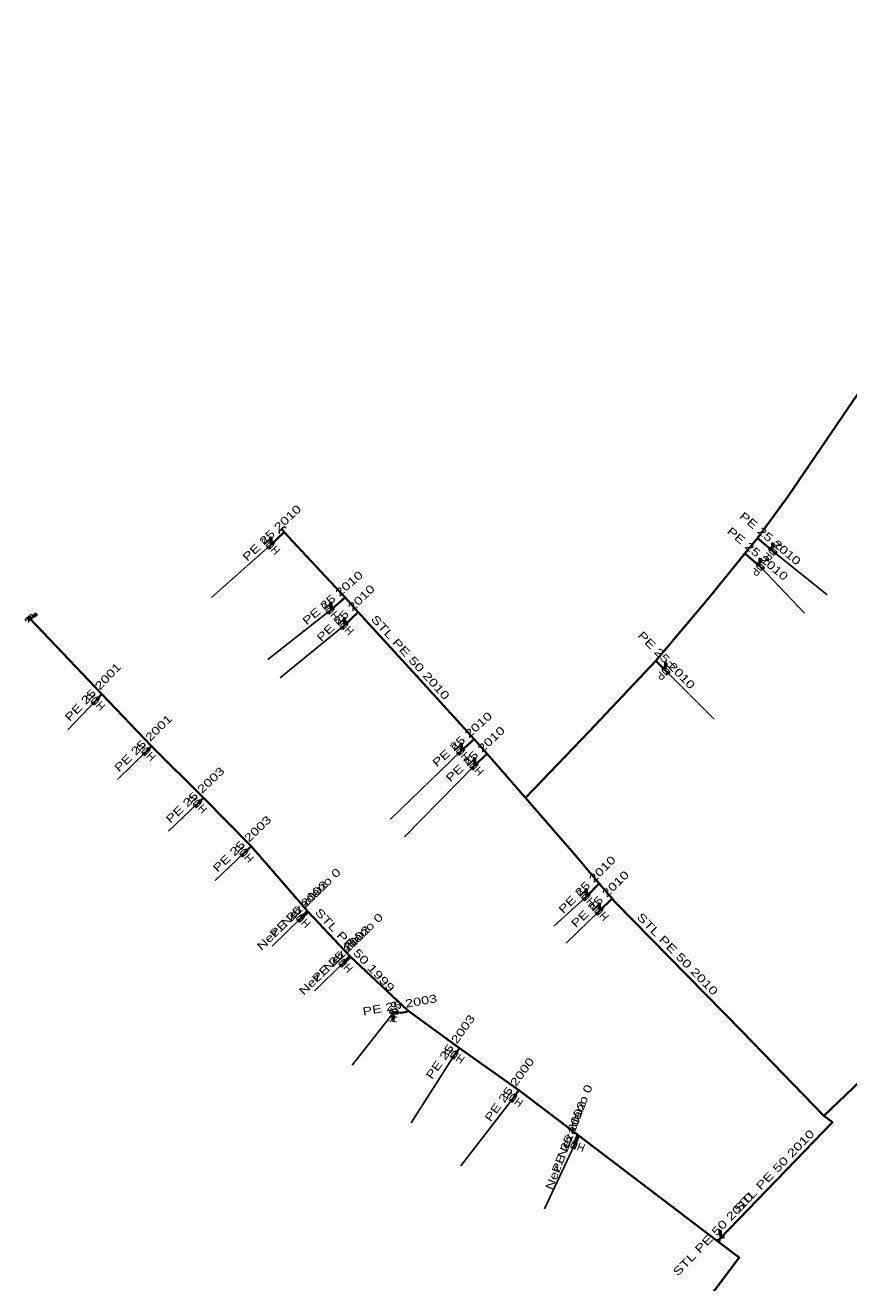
# Model space of a CAD drawing. Extents: x -737484 to -734496, y -1033882 to -1030666.
# Drawn here: x -736564.5 to -736461.6, y -1032578.8 to -1032421.6 of the extents above; entities that cross this region are included whole.
import ezdxf
from ezdxf.enums import TextEntityAlignment as Align

# ---------------------------------------------------------------- set-up
doc = ezdxf.new("R2010")
doc.units = 0
doc.header["$LTSCALE"] = 0.4
for name, color, linetype, lineweight in [('1', 7, 'Continuous', 13), ('18', 7, 'Continuous', 60), ('22', 7, 'Continuous', 25), ('5', 7, 'Continuous', 35), ('7', 7, 'Continuous', 35)]:
    doc.layers.add(name, color=color, linetype=linetype, lineweight=lineweight)
doc.layers.add('2', color=7, linetype='Continuous')

msp = doc.modelspace()

# ---------------------------------------------------------------- linework, layer by layer
at = {"layer": '1'}
for p, q in [((-736533.782, -1032486.023), (-736533.782, -1032485.673)), ((-736533.857, -1032486.598), (-736533.857, -1032486.098)), ((-736471.104, -1032487.331), (-736471.104, -1032486.831)), ((-736471.029, -1032486.756), (-736471.029, -1032486.406)), ((-736472.67, -1032489.253), (-736472.67, -1032488.753)), ((-736472.595, -1032488.678), (-736472.595, -1032488.328)), ((-736526.285, -1032494.161), (-736526.285, -1032493.811)), ((-736563.44, -1032495.519), (-736563.15, -1032495.323)), ((-736526.36, -1032494.736), (-736526.36, -1032494.236)), ((-736564.094, -1032496.258), (-736563.957, -1032495.778)), ((-736563.959, -1032495.779), (-736563.544, -1032495.499)), ((-736524.638, -1032496.644), (-736524.638, -1032496.144)), ((-736524.563, -1032496.069), (-736524.563, -1032495.719)), ((-736484.39, -1032501.721), (-736484.39, -1032501.371)), ((-736484.465, -1032502.296), (-736484.465, -1032501.796)), ((-736510.072, -1032512.351), (-736510.072, -1032511.851)), ((-736509.997, -1032511.776), (-736509.997, -1032511.426)), ((-736508.406, -1032514.191), (-736508.406, -1032513.691)), ((-736508.331, -1032513.616), (-736508.331, -1032513.266)), ((-736494.345, -1032529.963), (-736494.345, -1032529.613)), ((-736494.42, -1032530.538), (-736494.42, -1032530.038)), ((-736492.719, -1032531.76), (-736492.719, -1032531.41)), ((-736492.794, -1032532.335), (-736492.794, -1032531.835)), ((-736518.574, -1032545.488), (-736518.623, -1032545.835)), ((-736518.42, -1032544.93), (-736518.489, -1032545.425)), ((-736477.601, -1032572.67), (-736477.601, -1032572.32)), ((-736477.676, -1032573.245), (-736477.676, -1032572.745))]:
    msp.add_line(p, q, dxfattribs=at)
for points in [[(-736532.645, -1032485.123), (-736532.818, -1032484.942), (-736532.095, -1032484.251), (-736531.922, -1032484.432)], [(-736564.355, -1032496.086), (-736564.528, -1032495.906), (-736563.809, -1032495.211), (-736563.635, -1032495.391)]]:
    msp.add_lwpolyline(points, dxfattribs=at)
for points in [[(-736533.857, -1032485.598), (-736534.007, -1032485.598), (-736534.007, -1032486.098), (-736533.857, -1032486.098)], [(-736533.857, -1032485.598), (-736533.707, -1032485.598), (-736533.707, -1032486.098), (-736533.857, -1032486.098)], [(-736533.82, -1032485.636), (-736533.745, -1032485.636), (-736533.745, -1032486.061), (-736533.82, -1032486.061)], [(-736534.077, -1032487.089), (-736534.355, -1032486.801), (-736533.358, -1032486.394), (-736533.636, -1032486.106)], [(-736470.592, -1032487.499), (-736470.849, -1032487.805), (-736471.358, -1032486.856), (-736471.615, -1032487.162)], [(-736471.104, -1032486.331), (-736471.254, -1032486.331), (-736471.254, -1032486.831), (-736471.104, -1032486.831)], [(-736471.104, -1032486.331), (-736470.954, -1032486.331), (-736470.954, -1032486.831), (-736471.104, -1032486.831)], [(-736471.067, -1032486.369), (-736470.992, -1032486.369), (-736470.992, -1032486.794), (-736471.067, -1032486.794)], [(-736472.158, -1032489.421), (-736472.415, -1032489.727), (-736472.924, -1032488.778), (-736473.181, -1032489.084)], [(-736472.67, -1032488.253), (-736472.82, -1032488.253), (-736472.82, -1032488.753), (-736472.67, -1032488.753)], [(-736472.67, -1032488.253), (-736472.52, -1032488.253), (-736472.52, -1032488.753), (-736472.67, -1032488.753)], [(-736472.633, -1032488.291), (-736472.558, -1032488.291), (-736472.558, -1032488.716), (-736472.633, -1032488.716)], [(-736526.36, -1032493.736), (-736526.51, -1032493.736), (-736526.51, -1032494.236), (-736526.36, -1032494.236)], [(-736526.36, -1032493.736), (-736526.21, -1032493.736), (-736526.21, -1032494.236), (-736526.36, -1032494.236)], [(-736526.323, -1032493.774), (-736526.248, -1032493.774), (-736526.248, -1032494.199), (-736526.323, -1032494.199)], [(-736563.129, -1032495.219), (-736563.213, -1032495.095), (-736563.628, -1032495.375), (-736563.544, -1032495.499)], [(-736563.129, -1032495.219), (-736563.046, -1032495.344), (-736563.46, -1032495.623), (-736563.544, -1032495.499)], [(-736563.14, -1032495.271), (-736563.098, -1032495.333), (-736563.451, -1032495.571), (-736563.493, -1032495.509)], [(-736526.606, -1032495.214), (-736526.868, -1032494.913), (-736525.851, -1032494.558), (-736526.113, -1032494.257)], [(-736564.014, -1032496.021), (-736564.037, -1032496.015), (-736564.06, -1032496.005), (-736564.082, -1032495.994), (-736564.102, -1032495.98), (-736564.122, -1032495.965), (-736564.139, -1032495.949), (-736564.155, -1032495.93), (-736564.169, -1032495.909), (-736564.181, -1032495.888), (-736564.191, -1032495.865), (-736564.198, -1032495.843), (-736564.203, -1032495.818), (-736564.206, -1032495.793), (-736564.207, -1032495.769), (-736564.204, -1032495.745), (-736564.2, -1032495.72), (-736564.193, -1032495.696), (-736564.184, -1032495.674), (-736564.173, -1032495.652), (-736564.159, -1032495.631), (-736564.144, -1032495.612), (-736564.127, -1032495.595), (-736564.109, -1032495.579), (-736564.088, -1032495.565), (-736564.067, -1032495.552), (-736564.044, -1032495.543), (-736564.02, -1032495.536), (-736563.997, -1032495.531), (-736563.972, -1032495.527), (-736563.948, -1032495.527), (-736563.924, -1032495.529), (-736563.899, -1032495.534), (-736563.876, -1032495.54), (-736563.853, -1032495.549), (-736563.831, -1032495.561), (-736563.811, -1032495.574), (-736563.791, -1032495.59), (-736563.773, -1032495.606), (-736563.758, -1032495.625), (-736563.744, -1032495.645), (-736563.731, -1032495.667), (-736563.722, -1032495.69), (-736563.714, -1032495.713), (-736563.71, -1032495.737), (-736563.706, -1032495.761), (-736563.706, -1032495.786), (-736563.708, -1032495.81), (-736563.713, -1032495.834), (-736563.719, -1032495.858), (-736563.728, -1032495.881), (-736563.74, -1032495.903), (-736563.753, -1032495.923), (-736563.769, -1032495.943), (-736563.785, -1032495.961), (-736563.804, -1032495.976), (-736563.824, -1032495.99), (-736563.846, -1032496.002), (-736563.869, -1032496.012), (-736563.892, -1032496.02), (-736563.916, -1032496.024), (-736563.941, -1032496.027), (-736563.965, -1032496.028), (-736563.989, -1032496.025)], [(-736563.786, -1032495.817), (-736563.79, -1032495.833), (-736563.796, -1032495.849), (-736563.805, -1032495.865), (-736563.814, -1032495.88), (-736563.824, -1032495.893), (-736563.837, -1032495.905), (-736563.85, -1032495.916), (-736563.864, -1032495.926), (-736563.879, -1032495.935), (-736563.894, -1032495.942), (-736563.911, -1032495.946), (-736563.928, -1032495.95), (-736563.945, -1032495.952), (-736563.962, -1032495.953), (-736563.979, -1032495.951), (-736563.996, -1032495.948), (-736564.012, -1032495.944), (-736564.029, -1032495.937), (-736564.044, -1032495.929), (-736564.059, -1032495.92), (-736564.072, -1032495.909), (-736564.084, -1032495.897), (-736564.095, -1032495.884), (-736564.105, -1032495.87), (-736564.114, -1032495.854), (-736564.121, -1032495.839), (-736564.125, -1032495.823), (-736564.129, -1032495.806), (-736564.131, -1032495.789), (-736564.131, -1032495.771), (-736564.13, -1032495.754), (-736564.127, -1032495.737), (-736564.122, -1032495.721), (-736564.116, -1032495.705), (-736564.108, -1032495.689), (-736564.099, -1032495.675), (-736564.088, -1032495.662), (-736564.076, -1032495.65), (-736564.063, -1032495.638), (-736564.049, -1032495.628), (-736564.033, -1032495.62), (-736564.018, -1032495.613), (-736564.001, -1032495.608), (-736563.985, -1032495.604), (-736563.968, -1032495.603), (-736563.95, -1032495.603), (-736563.934, -1032495.604), (-736563.916, -1032495.607), (-736563.9, -1032495.612), (-736563.884, -1032495.618), (-736563.868, -1032495.626), (-736563.854, -1032495.635), (-736563.841, -1032495.645), (-736563.828, -1032495.657), (-736563.817, -1032495.671), (-736563.807, -1032495.685), (-736563.799, -1032495.7), (-736563.792, -1032495.715), (-736563.788, -1032495.732), (-736563.783, -1032495.749), (-736563.782, -1032495.766), (-736563.781, -1032495.783), (-736563.782, -1032495.8)], [(-736564.103, -1032495.743), (-736564.098, -1032495.728), (-736564.093, -1032495.716), (-736564.087, -1032495.702), (-736564.078, -1032495.69), (-736564.07, -1032495.678), (-736564.059, -1032495.668), (-736564.047, -1032495.658), (-736564.035, -1032495.65), (-736564.023, -1032495.643), (-736564.009, -1032495.637), (-736563.995, -1032495.632), (-736563.981, -1032495.629), (-736563.965, -1032495.627), (-736563.951, -1032495.627), (-736563.937, -1032495.628), (-736563.922, -1032495.631), (-736563.907, -1032495.636), (-736563.894, -1032495.64), (-736563.881, -1032495.647), (-736563.868, -1032495.655), (-736563.857, -1032495.664), (-736563.847, -1032495.675), (-736563.837, -1032495.686), (-736563.829, -1032495.699), (-736563.821, -1032495.711), (-736563.815, -1032495.724), (-736563.811, -1032495.739), (-736563.808, -1032495.753), (-736563.806, -1032495.768), (-736563.806, -1032495.782), (-736563.807, -1032495.797), (-736563.81, -1032495.811), (-736563.814, -1032495.826), (-736563.819, -1032495.84), (-736563.826, -1032495.852), (-736563.834, -1032495.865), (-736563.843, -1032495.877), (-736563.854, -1032495.887), (-736563.865, -1032495.896), (-736563.877, -1032495.905), (-736563.89, -1032495.912), (-736563.903, -1032495.918), (-736563.918, -1032495.923), (-736563.932, -1032495.926), (-736563.946, -1032495.927), (-736563.961, -1032495.927), (-736563.976, -1032495.926), (-736563.99, -1032495.924), (-736564.005, -1032495.92), (-736564.018, -1032495.914), (-736564.031, -1032495.907), (-736564.043, -1032495.899), (-736564.056, -1032495.891), (-736564.066, -1032495.88), (-736564.075, -1032495.868), (-736564.084, -1032495.856), (-736564.091, -1032495.844), (-736564.096, -1032495.83), (-736564.102, -1032495.816), (-736564.105, -1032495.802), (-736564.106, -1032495.787), (-736564.107, -1032495.772), (-736564.105, -1032495.758)], [(-736564.029, -1032495.76), (-736564.027, -1032495.753), (-736564.025, -1032495.747), (-736564.022, -1032495.74), (-736564.017, -1032495.734), (-736564.013, -1032495.728), (-736564.007, -1032495.722), (-736564.002, -1032495.718), (-736563.995, -1032495.713), (-736563.989, -1032495.71), (-736563.983, -1032495.706), (-736563.975, -1032495.705), (-736563.969, -1032495.703), (-736563.961, -1032495.702), (-736563.954, -1032495.702), (-736563.946, -1032495.702), (-736563.94, -1032495.704), (-736563.932, -1032495.707), (-736563.925, -1032495.708), (-736563.919, -1032495.712), (-736563.912, -1032495.716), (-736563.907, -1032495.721), (-736563.901, -1032495.726), (-736563.896, -1032495.731), (-736563.892, -1032495.738), (-736563.889, -1032495.744), (-736563.886, -1032495.751), (-736563.883, -1032495.758), (-736563.882, -1032495.765), (-736563.881, -1032495.773), (-736563.881, -1032495.78), (-736563.882, -1032495.787), (-736563.883, -1032495.794), (-736563.885, -1032495.801), (-736563.888, -1032495.808), (-736563.891, -1032495.815), (-736563.895, -1032495.821), (-736563.9, -1032495.827), (-736563.904, -1032495.832), (-736563.911, -1032495.837), (-736563.916, -1032495.841), (-736563.923, -1032495.844), (-736563.93, -1032495.848), (-736563.937, -1032495.85), (-736563.944, -1032495.852), (-736563.951, -1032495.853), (-736563.959, -1032495.853), (-736563.966, -1032495.852), (-736563.973, -1032495.851), (-736563.981, -1032495.848), (-736563.987, -1032495.846), (-736563.994, -1032495.843), (-736564, -1032495.839), (-736564.006, -1032495.834), (-736564.011, -1032495.829), (-736564.016, -1032495.823), (-736564.02, -1032495.817), (-736564.023, -1032495.81), (-736564.027, -1032495.804), (-736564.028, -1032495.796), (-736564.031, -1032495.79), (-736564.031, -1032495.782), (-736564.032, -1032495.775), (-736564.031, -1032495.768)], [(-736524.858, -1032497.135), (-736525.136, -1032496.847), (-736524.139, -1032496.44), (-736524.417, -1032496.152)], [(-736524.638, -1032495.644), (-736524.788, -1032495.644), (-736524.788, -1032496.144), (-736524.638, -1032496.144)], [(-736524.638, -1032495.644), (-736524.488, -1032495.644), (-736524.488, -1032496.144), (-736524.638, -1032496.144)], [(-736524.601, -1032495.682), (-736524.526, -1032495.682), (-736524.526, -1032496.107), (-736524.601, -1032496.107)], [(-736484.465, -1032501.296), (-736484.615, -1032501.296), (-736484.615, -1032501.796), (-736484.465, -1032501.796)], [(-736484.465, -1032501.296), (-736484.315, -1032501.296), (-736484.315, -1032501.796), (-736484.465, -1032501.796)], [(-736484.428, -1032501.334), (-736484.353, -1032501.334), (-736484.353, -1032501.759), (-736484.428, -1032501.759)], [(-736483.97, -1032502.508), (-736484.252, -1032502.79), (-736484.677, -1032501.801), (-736484.959, -1032502.083)], [(-736555.932, -1032506.558), (-736556.22, -1032506.28), (-736555.237, -1032505.839), (-736555.525, -1032505.561)], [(-736549.622, -1032512.874), (-736549.904, -1032512.592), (-736548.915, -1032512.167), (-736549.197, -1032511.885)], [(-736510.309, -1032512.834), (-736510.577, -1032512.536), (-736509.566, -1032512.165), (-736509.834, -1032511.867)], [(-736510.072, -1032511.351), (-736510.222, -1032511.351), (-736510.222, -1032511.851), (-736510.072, -1032511.851)], [(-736510.072, -1032511.351), (-736509.922, -1032511.351), (-736509.922, -1032511.851), (-736510.072, -1032511.851)], [(-736510.035, -1032511.389), (-736509.96, -1032511.389), (-736509.96, -1032511.814), (-736510.035, -1032511.814)], [(-736508.635, -1032514.678), (-736508.908, -1032514.385), (-736507.903, -1032513.996), (-736508.176, -1032513.703)], [(-736508.406, -1032513.191), (-736508.556, -1032513.191), (-736508.556, -1032513.691), (-736508.406, -1032513.691)], [(-736508.406, -1032513.191), (-736508.256, -1032513.191), (-736508.256, -1032513.691), (-736508.406, -1032513.691)], [(-736508.369, -1032513.229), (-736508.294, -1032513.229), (-736508.294, -1032513.654), (-736508.369, -1032513.654)], [(-736543.198, -1032519.376), (-736543.471, -1032519.083), (-736542.466, -1032518.694), (-736542.739, -1032518.401)], [(-736537.379, -1032525.541), (-736537.657, -1032525.253), (-736536.66, -1032524.846), (-736536.938, -1032524.558)], [(-736494.42, -1032529.538), (-736494.57, -1032529.538), (-736494.57, -1032530.038), (-736494.42, -1032530.038)], [(-736494.42, -1032529.538), (-736494.27, -1032529.538), (-736494.27, -1032530.038), (-736494.42, -1032530.038)], [(-736494.383, -1032529.576), (-736494.308, -1032529.576), (-736494.308, -1032530.001), (-736494.383, -1032530.001)], [(-736494.632, -1032531.032), (-736494.914, -1032530.75), (-736493.925, -1032530.325), (-736494.207, -1032530.043)], [(-736492.794, -1032531.335), (-736492.944, -1032531.335), (-736492.944, -1032531.835), (-736492.794, -1032531.835)], [(-736492.794, -1032531.335), (-736492.644, -1032531.335), (-736492.644, -1032531.835), (-736492.794, -1032531.835)], [(-736492.757, -1032531.373), (-736492.682, -1032531.373), (-736492.682, -1032531.798), (-736492.757, -1032531.798)], [(-736530.279, -1032533.7), (-736530.557, -1032533.412), (-736529.56, -1032533.005), (-736529.838, -1032532.717)], [(-736493.014, -1032532.826), (-736493.292, -1032532.538), (-736492.295, -1032532.131), (-736492.573, -1032531.843)], [(-736524.999, -1032539.31), (-736525.277, -1032539.022), (-736524.28, -1032538.615), (-736524.558, -1032538.327)], [(-736518.942, -1032545.058), (-736518.887, -1032544.662), (-736517.952, -1032545.197), (-736517.897, -1032544.801)], [(-736518.559, -1032545.92), (-736518.707, -1032545.899), (-736518.638, -1032545.404), (-736518.489, -1032545.425)], [(-736518.59, -1032545.877), (-736518.664, -1032545.867), (-736518.605, -1032545.446), (-736518.531, -1032545.456)], [(-736518.559, -1032545.92), (-736518.41, -1032545.941), (-736518.341, -1032545.446), (-736518.489, -1032545.425)], [(-736510.992, -1032550.813), (-736511.32, -1032550.583), (-736510.419, -1032549.994), (-736510.747, -1032549.764)], [(-736503.682, -1032556.211), (-736504.005, -1032555.975), (-736503.094, -1032555.402), (-736503.417, -1032555.166)], [(-736495.872, -1032562.057), (-736496.245, -1032561.914), (-736495.514, -1032561.123), (-736495.887, -1032560.98)], [(-736477.676, -1032572.245), (-736477.826, -1032572.245), (-736477.826, -1032572.745), (-736477.676, -1032572.745)], [(-736477.676, -1032572.245), (-736477.526, -1032572.245), (-736477.526, -1032572.745), (-736477.676, -1032572.745)], [(-736477.639, -1032572.283), (-736477.564, -1032572.283), (-736477.564, -1032572.708), (-736477.639, -1032572.708)], [(-736477.807, -1032573.813), (-736478.239, -1032573.396), (-736477.112, -1032573.093), (-736477.544, -1032572.676)]]:
    msp.add_lwpolyline(points, close=True, dxfattribs=at)
at = {"layer": '18'}
for p, q in [((-736530.059, -1032533.209), (-736529.214, -1032532.386)), ((-736523.928, -1032537.993), (-736524.779, -1032538.819)), ((-736495.42, -1032560.337), (-736495.879, -1032561.519))]:
    msp.add_line(p, q, dxfattribs=at)
at = {"layer": '22'}
for p, q in [((-736533.857, -1032486.598), (-736541.254, -1032493.119)), ((-736471.104, -1032487.331), (-736464.295, -1032492.796)), ((-736472.67, -1032489.253), (-736467.116, -1032495.087)), ((-736526.36, -1032494.736), (-736534.218, -1032500.897)), ((-736524.638, -1032496.644), (-736532.662, -1032503.193)), ((-736484.465, -1032502.296), (-736478.398, -1032508.353)), ((-736555.729, -1032506.06), (-736559.175, -1032509.683)), ((-736549.41, -1032512.38), (-736552.972, -1032515.889)), ((-736510.072, -1032512.351), (-736518.886, -1032520.821)), ((-736508.406, -1032514.191), (-736517.108, -1032523.043)), ((-736542.969, -1032518.889), (-736546.601, -1032522.325)), ((-736537.159, -1032525.05), (-736540.776, -1032528.502)), ((-736494.42, -1032530.538), (-736498.446, -1032534.196)), ((-736492.794, -1032532.335), (-736496.915, -1032536.32)), ((-736530.059, -1032533.209), (-736533.639, -1032536.7)), ((-736524.779, -1032538.819), (-736528.367, -1032542.301)), ((-736518.42, -1032544.93), (-736523.639, -1032551.575)), ((-736510.87, -1032550.289), (-736516.288, -1032558.763)), ((-736503.55, -1032555.689), (-736510.08, -1032564.154)), ((-736495.88, -1032561.519), (-736499.624, -1032569.545))]:
    msp.add_line(p, q, dxfattribs=at)
at = {"layer": '5'}
msp.add_line((-736477.985, -1032573.565), (-736477.676, -1032573.245), dxfattribs=at)
for points in [[(-736501.99, -1032518.186), (-736494.005, -1032509.824), (-736485.693, -1032501.05), (-736479.04, -1032493.131), (-736474.587, -1032487.629), (-736473.007, -1032485.735), (-736469.184, -1032480.478), (-736461.088, -1032468.614), (-736452.802, -1032456.612), (-736451.372, -1032454.659), (-736448.439, -1032450.843), (-736441.296, -1032438.651), (-736435.822, -1032429.517), (-736434.551, -1032427.173), (-736428.273, -1032416.819)], [(-736501.99, -1032518.186), (-736506.772, -1032512.68), (-736508.404, -1032510.855), (-736515.17, -1032503.435), (-736522.901, -1032494.958), (-736524.526, -1032493.148), (-736529.402, -1032487.948), (-736532.168, -1032484.995), (-736532.457, -1032484.597)], [(-736564.169, -1032495.559), (-736563.957, -1032495.778), (-736554.93, -1032505.22), (-736548.74, -1032511.72), (-736542.23, -1032518.19), (-736536.3, -1032524.23), (-736529.215, -1032532.386), (-736523.929, -1032537.994), (-736516.69, -1032544.76), (-736510.26, -1032549.43), (-736502.84, -1032554.71), (-736495.421, -1032560.338), (-736477.985, -1032573.565)], [(-736501.99, -1032518.186), (-736495.974, -1032525.141), (-736492.77, -1032528.88), (-736491.179, -1032530.753), (-736490.828, -1032531.147), (-736474.92, -1032547.348), (-736464.706, -1032557.917)], [(-736434.644, -1032529.078), (-736443.04, -1032537.119), (-736447.478, -1032541.53), (-736460.126, -1032553.515), (-736464.706, -1032557.917)], [(-736477.676, -1032573.245), (-736463.643, -1032558.703), (-736464.706, -1032557.917)], [(-736477.985, -1032573.565), (-736475.29, -1032575.61), (-736485.57, -1032589.34), (-736485.04, -1032590.3), (-736482.57, -1032592.15), (-736460.8, -1032607.15), (-736458.64, -1032608.39), (-736440.23, -1032620.29), (-736437.73, -1032621.95), (-736415.21, -1032636.47), (-736414.2, -1032637.15), (-736413.09, -1032637.79), (-736374.31, -1032664.74), (-736370.11, -1032667.36), (-736368.25, -1032668.68), (-736350.272, -1032680.583), (-736343.55, -1032685), (-736325.04, -1032697.15), (-736315.65, -1032703.23), (-736278.9, -1032729.88)]]:
    msp.add_lwpolyline(points, dxfattribs=at)
at = {"layer": '7'}
for p, q in [((-736532.168, -1032484.995), (-736533.857, -1032486.598)), ((-736473.007, -1032485.735), (-736471.104, -1032487.331)), ((-736474.587, -1032487.629), (-736472.67, -1032489.253)), ((-736524.526, -1032493.148), (-736526.36, -1032494.736)), ((-736522.901, -1032494.958), (-736524.638, -1032496.644)), ((-736485.693, -1032501.05), (-736484.465, -1032502.296)), ((-736554.93, -1032505.22), (-736555.729, -1032506.06)), ((-736508.404, -1032510.855), (-736510.072, -1032512.351)), ((-736548.74, -1032511.72), (-736549.41, -1032512.38)), ((-736506.772, -1032512.68), (-736508.406, -1032514.191)), ((-736542.23, -1032518.19), (-736542.969, -1032518.889)), ((-736536.3, -1032524.23), (-736537.159, -1032525.05)), ((-736492.77, -1032528.88), (-736494.42, -1032530.538)), ((-736491.179, -1032530.753), (-736492.794, -1032532.335)), ((-736529.215, -1032532.386), (-736530.059, -1032533.209)), ((-736523.929, -1032537.994), (-736524.779, -1032538.819)), ((-736510.26, -1032549.43), (-736510.87, -1032550.289)), ((-736502.84, -1032554.71), (-736503.55, -1032555.689)), ((-736495.421, -1032560.338), (-736495.88, -1032561.519))]:
    msp.add_line(p, q, dxfattribs=at)
msp.add_lwpolyline([(-736516.69, -1032544.76), (-736516.83, -1032544.9), (-736517.59, -1032545.04), (-736518.42, -1032544.93)], dxfattribs=at)

# ---------------------------------------------------------------- texts
at = {"layer": '18', "width": 1.35}
for rotation, p in [(44.244, (-736529.9844, -1032532.4391)), (44.146, (-736524.7017, -1032538.0472)), (68.778, (-736496.115, -1032560.7465))]:
    msp.add_text('Nez. Nezadáno 0', height=1, rotation=rotation, dxfattribs=at).set_placement(p, align=Align.CENTER)
at = {"layer": '2', "width": 0.95}
for rotation, p in [(134, (-736533.4964, -1032486.2508)), (230, (-736471.4866, -1032487.0091)), (230, (-736473.0526, -1032488.9311)), (131, (-736525.9826, -1032494.4075)), (134, (-736524.2774, -1032496.2968)), (225, (-736484.8179, -1032501.9419)), (136, (-736555.3812, -1032505.6996)), (135, (-736549.0559, -1032512.0261)), (132, (-736509.6997, -1032512.0161)), (133, (-736508.04, -1032513.8495)), (133, (-736542.603, -1032518.5475)), (134, (-736536.7984, -1032524.7028)), (135, (-736494.0659, -1032530.1841)), (134, (-736492.4334, -1032531.9878)), (134, (-736529.6984, -1032532.8618)), (134, (-736524.4184, -1032538.4718)), (82, (-736517.9243, -1032544.9991)), (145, (-736510.5827, -1032549.8791)), (144, (-736503.2556, -1032555.284)), (159, (-736495.7003, -1032561.0517))]:
    msp.add_text('HUP', height=1, rotation=rotation, dxfattribs=at).set_placement(p, align=Align.CENTER)
at = {"layer": '5', "width": 1.4}
for s, rotation, p in [('STL PE 50 2010', 312.365, (-736516.75, -1032500.9591)), ('STL PE 50 1999', 313.307, (-736523.6804, -1032537.528)), ('STL PE 50 2010', 314.477, (-736483.3593, -1032538.0382)), ('STL PE 50 2010', 46.02, (-736470.5596, -1032565.1507)), ('STL PE 50 2010', 46.002, (-736478.1891, -1032573.0573))]:
    msp.add_text(s, height=1, rotation=rotation, dxfattribs=at).set_placement(p, align=Align.CENTER)
at = {"layer": '7', "width": 1.35}
for s, rotation, p in [('PE 25 2010', 43.504, (-736533.3562, -1032485.4334)), ('PE 25 2010', 320.014, (-736471.7338, -1032486.15)), ('PE 25 2010', 319.73, (-736473.3047, -1032488.0587)), ('PE 25 2010', 40.888, (-736525.7703, -1032493.5639)), ('PE 25 2010', 44.146, (-736524.1177, -1032495.4418)), ('PE 25 2010', 314.583, (-736484.7228, -1032501.3215)), ('PE 25 2001', 46.433, (-736555.6914, -1032505.2946)), ('PE 25 2001', 44.569, (-736549.4254, -1032511.6935)), ('PE 25 2010', 41.888, (-736509.5713, -1032511.2297)), ('PE 25 2010', 42.76, (-736507.928, -1032513.0682)), ('PE 25 2003', 43.407, (-736542.9426, -1032518.1753)), ('PE 25 2003', 43.669, (-736537.0747, -1032524.2773)), ('PE 25 2010', 45.139, (-736493.9491, -1032529.3557)), ('PE 25 2010', 44.409, (-736492.3359, -1032531.1859)), ('PE 25 2002', 44.278, (-736529.9851, -1032532.4386)), ('PE 25 2002', 44.145, (-736524.7012, -1032538.0475)), ('PE 25 2003', 10.437, (-736517.6146, -1032544.5356)), ('PE 25 2003', 54.62, (-736510.9726, -1032549.5695)), ('PE 25 2000', 54.049, (-736503.5999, -1032554.9055)), ('PE 25 2002', 68.761, (-736496.1156, -1032560.7471))]:
    msp.add_text(s, height=1, rotation=rotation, dxfattribs=at).set_placement(p, align=Align.CENTER)

doc.saveas('drawing.dxf')
